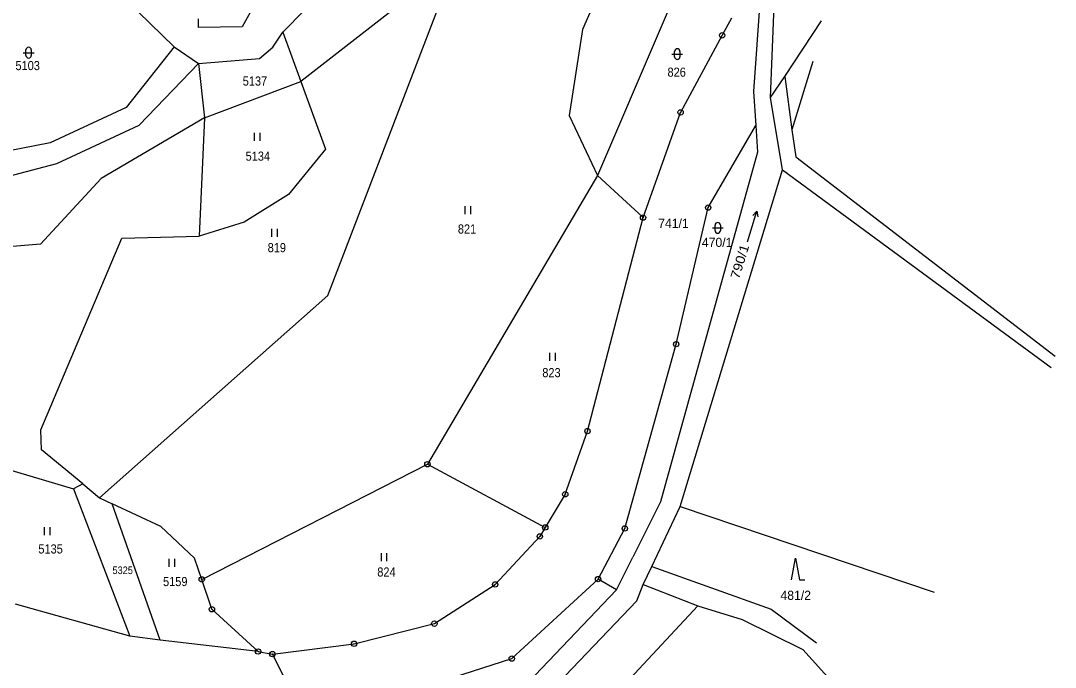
# Model space of a CAD drawing. Extents: x -665688 to -664583, y -1006118 to -1004927.
# Drawn here: x -664775.4 to -664582.7, y -1005645.6 to -1005525.2 of the extents above; entities that cross this region are included whole.
import ezdxf
from ezdxf.enums import TextEntityAlignment as Align

# ---------------------------------------------------------------- set-up
doc = ezdxf.new("R2010")
doc.units = 0
doc.header["$LTSCALE"] = 0.68
for name, color, linetype, lineweight in [('1', 7, 'Continuous', 25), ('13', 7, 'Continuous', 25), ('24', 7, 'Continuous', 25), ('25', 7, 'Continuous', 25)]:
    doc.layers.add(name, color=color, linetype=linetype, lineweight=lineweight)
doc.layers.add('18', color=7, linetype='Continuous')

msp = doc.modelspace()

# ---------------------------------------------------------------- linework, layer by layer
at = {"layer": '1'}
for p, q in [((-664637.47, -1005518.22), (-664638.88, -1005538.4)), ((-664635.72, -1005539.55), (-664634.86, -1005516.66)), ((-664753.52, -1005523.57), (-664746.83, -1005530.12)), ((-664633.1, -1005535.6), (-664626.24, -1005525.26)), ((-664746.83, -1005530.12), (-664742.26, -1005533.2)), ((-664742.26, -1005533.2), (-664741.2, -1005543.33)), ((-664627.87, -1005532.84), (-664631.74, -1005545.57)), ((-664635.72, -1005539.55), (-664633.1, -1005535.6)), ((-664633.1, -1005535.6), (-664631.74, -1005545.57)), ((-664741.2, -1005543.33), (-664723.24, -1005536.54)), ((-664741.2, -1005543.33), (-664742.16, -1005565.36)), ((-664647.35, -1005560.03), (-664638.47, -1005544.74)), ((-664631.74, -1005545.57), (-664631.05, -1005550.6)), ((-664638.14, -1005549.72), (-664656.22, -1005614.79)), ((-664631.05, -1005550.6), (-664582.69, -1005587.66)), ((-664633.51, -1005553.01), (-664583.48, -1005589.82)), ((-664659.48, -1005561.89), (-664667.97, -1005554.06)), ((-664741.69, -1005629.24), (-664699.64, -1005607.8)), ((-664763.84, -1005611.47), (-664765.6, -1005612.38)), ((-664673.97, -1005613.4), (-664677.71, -1005619.57)), ((-664656.22, -1005614.79), (-664661.41, -1005625.11)), ((-664652.59, -1005615.68), (-664605.24, -1005631.61)), ((-664667.85, -1005629.18), (-664662.88, -1005619.76)), ((-664664.44, -1005631.16), (-664661.41, -1005625.11)), ((-664657.84, -1005626.82), (-664635.61, -1005634.8)), ((-664664.44, -1005631.16), (-664667.85, -1005629.18)), ((-664660.62, -1005633.25), (-664659.43, -1005630.2)), ((-664659.43, -1005630.2), (-664649.3, -1005634.13)), ((-664664.44, -1005631.16), (-664682.13, -1005649.71)), ((-664678.66, -1005652.03), (-664660.62, -1005633.25)), ((-664649.3, -1005634.13), (-664641.05, -1005636.72)), ((-664635.61, -1005634.8), (-664627.17, -1005641.05)), ((-664641.05, -1005636.72), (-664629.72, -1005642.29)), ((-664749.4, -1005640.58), (-664755.06, -1005639.78)), ((-664629.72, -1005642.29), (-664623.93, -1005648.66))]:
    msp.add_line(p, q, dxfattribs=at)
for points in [[(-664685.29, -1005447.42), (-664678.21, -1005458.37), (-664669.44, -1005467.93), (-664668.54, -1005477.26), (-664674.88, -1005479.83), (-664681.01, -1005483.45), (-664689.57, -1005496.01), (-664699.21, -1005490.29), (-664709.59, -1005492.53), (-664717.15, -1005498.25), (-664721.04, -1005508.79), (-664724.28, -1005514.32), (-664727.9, -1005516.23), (-664729.33, -1005517.63), (-664734.13, -1005526.39), (-664742.32, -1005526.52), (-664742.32, -1005524.88)], [(-664663.52, -1005487.96), (-664655.75, -1005492.6), (-664670.76, -1005526.88), (-664673.24, -1005542.89), (-664667.97, -1005554.06), (-664699.64, -1005607.8)], [(-664643.02, -1005495.8), (-664644.05, -1005498.2), (-664667.97, -1005554.06)], [(-664699.89, -1005512.36), (-664705.92, -1005523.12), (-664723.24, -1005536.54)], [(-664760.73, -1005614.05), (-664718.22, -1005576.38), (-664695.53, -1005517.33)], [(-664746.83, -1005530.12), (-664755.79, -1005541.41), (-664769.9, -1005547.96), (-664777.87, -1005549.55), (-664809.58, -1005552.27), (-664806.9, -1005547.53), (-664795.07, -1005526.57), (-664788.63, -1005523.13)], [(-664643.03, -1005524.78), (-664644.74, -1005527.96), (-664652.48, -1005542.3)], [(-664742.26, -1005533.2), (-664730.95, -1005532.27), (-664728.47, -1005530.19), (-664726.59, -1005527.38)], [(-664857.56, -1005568.28), (-664837.85, -1005564.71), (-664809.01, -1005556.42), (-664777.88, -1005554.25), (-664768.66, -1005551.79), (-664753.33, -1005544.68), (-664742.26, -1005533.2)], [(-664652.59, -1005615.68), (-664633.51, -1005553.01), (-664635.72, -1005539.55)], [(-664638.88, -1005538.4), (-664638.47, -1005544.74), (-664638.14, -1005549.72)], [(-664741.2, -1005543.33), (-664760.39, -1005554.64), (-664771.75, -1005566.81), (-664853.43, -1005573.61), (-664857.56, -1005568.28)], [(-664673.97, -1005613.4), (-664669.83, -1005601.64), (-664659.48, -1005561.89), (-664652.48, -1005542.3)], [(-664662.88, -1005619.76), (-664653.31, -1005585.45), (-664647.35, -1005560.03)], [(-664809.2, -1005599.44), (-664765.6, -1005612.38), (-664755.06, -1005639.78), (-664776.38, -1005633.86)], [(-664699.64, -1005607.8), (-664677.71, -1005619.57), (-664678.71, -1005621.24)], [(-664731.2, -1005642.66), (-664749.4, -1005640.58), (-664758.34, -1005615.17)], [(-664659.43, -1005630.2), (-664657.84, -1005626.82), (-664652.59, -1005615.68)], [(-664728.52, -1005643.15), (-664713.31, -1005641.23), (-664698.36, -1005637.48), (-664687.03, -1005630.18), (-664678.71, -1005621.24)], [(-664723.34, -1005653.6), (-664718.83, -1005655.21), (-664683.93, -1005643.99), (-664667.85, -1005629.18)], [(-664695.53, -1005671.67), (-664673.75, -1005660.42), (-664649.3, -1005634.13)]]:
    msp.add_lwpolyline(points, dxfattribs=at)
at = {"layer": '13'}
for p, q in [((-664726.59, -1005527.38), (-664723.24, -1005536.54)), ((-664771.68, -1005601.4), (-664756.56, -1005565.69)), ((-664756.56, -1005565.69), (-664742.16, -1005565.36))]:
    msp.add_line(p, q, dxfattribs=at)
for points in [[(-664701.58, -1005496.46), (-664713.18, -1005504.69), (-664714.32, -1005514.93), (-664726.59, -1005527.38)], [(-664723.24, -1005536.54), (-664718.63, -1005549.18), (-664725.52, -1005557.62), (-664733.81, -1005562.76), (-664742.16, -1005565.36)], [(-664763.84, -1005611.47), (-664771.53, -1005605.1), (-664771.68, -1005601.4)], [(-664763.84, -1005611.47), (-664760.73, -1005614.05), (-664758.34, -1005615.17)], [(-664741.69, -1005629.24), (-664743.04, -1005625.31), (-664749.31, -1005619.42), (-664758.34, -1005615.17)], [(-664731.2, -1005642.66), (-664739.79, -1005634.8), (-664741.69, -1005629.24)], [(-664731.2, -1005642.66), (-664728.52, -1005643.15), (-664723.34, -1005653.6), (-664724.77, -1005653.7)]]:
    msp.add_lwpolyline(points, dxfattribs=at)
at = {"layer": '24'}
for centre, radius in [((-664644.74, -1005527.96), 0.5), ((-664644.74, -1005527.96), 0.032), ((-664652.48, -1005542.3), 0.5), ((-664652.48, -1005542.3), 0.032), ((-664647.35, -1005560.03), 0.5), ((-664647.35, -1005560.03), 0.032), ((-664659.48, -1005561.89), 0.5), ((-664659.48, -1005561.89), 0.032), ((-664653.31, -1005585.45), 0.5), ((-664653.31, -1005585.45), 0.032), ((-664669.83, -1005601.64), 0.5), ((-664669.83, -1005601.64), 0.032), ((-664699.64, -1005607.8), 0.5), ((-664699.64, -1005607.8), 0.032), ((-664673.97, -1005613.4), 0.5), ((-664673.97, -1005613.4), 0.032), ((-664677.71, -1005619.57), 0.5), ((-664677.71, -1005619.57), 0.032), ((-664662.88, -1005619.76), 0.5), ((-664662.88, -1005619.76), 0.032), ((-664678.71, -1005621.24), 0.5), ((-664678.71, -1005621.24), 0.032), ((-664741.69, -1005629.24), 0.5), ((-664741.69, -1005629.24), 0.032), ((-664687.03, -1005630.18), 0.5), ((-664687.03, -1005630.18), 0.032), ((-664667.85, -1005629.18), 0.5), ((-664667.85, -1005629.18), 0.032), ((-664739.79, -1005634.8), 0.5), ((-664739.79, -1005634.8), 0.032), ((-664698.36, -1005637.48), 0.5), ((-664698.36, -1005637.48), 0.032), ((-664713.31, -1005641.23), 0.5), ((-664713.31, -1005641.23), 0.032), ((-664731.2, -1005642.66), 0.5), ((-664731.2, -1005642.66), 0.032), ((-664728.52, -1005643.15), 0.5), ((-664728.52, -1005643.15), 0.032), ((-664683.93, -1005643.99), 0.5), ((-664683.93, -1005643.99), 0.032)]:
    msp.add_circle(centre, radius, dxfattribs=at)
at = {"layer": '25'}
for p, q in [((-664774.93, -1005531.19), (-664772.93, -1005531.19)), ((-664774.43, -1005531.69), (-664774.43, -1005530.69)), ((-664773.43, -1005530.69), (-664773.43, -1005531.69)), ((-664654.11, -1005531.45), (-664652.11, -1005531.45)), ((-664653.61, -1005531.95), (-664653.61, -1005530.95)), ((-664652.61, -1005530.95), (-664652.61, -1005531.95)), ((-664731.837, -1005547.585), (-664731.837, -1005546.085)), ((-664730.803, -1005547.585), (-664730.803, -1005546.085)), ((-664692.597, -1005561.275), (-664692.597, -1005559.775)), ((-664691.563, -1005561.275), (-664691.563, -1005559.775)), ((-664640.052, -1005566.394), (-664638.268, -1005560.666)), ((-664728.637, -1005565.485), (-664728.637, -1005563.985)), ((-664727.603, -1005565.485), (-664727.603, -1005563.985)), ((-664646.57, -1005563.8), (-664644.57, -1005563.8)), ((-664646.07, -1005564.3), (-664646.07, -1005563.3)), ((-664645.07, -1005563.3), (-664645.07, -1005564.3)), ((-664676.817, -1005588.545), (-664676.817, -1005587.045)), ((-664675.783, -1005588.545), (-664675.783, -1005587.045)), ((-664770.967, -1005621.005), (-664770.967, -1005619.505)), ((-664769.933, -1005621.005), (-664769.933, -1005619.505)), ((-664708.217, -1005625.875), (-664708.217, -1005624.375)), ((-664707.183, -1005625.875), (-664707.183, -1005624.375)), ((-664747.747, -1005626.885), (-664747.747, -1005625.385)), ((-664746.713, -1005626.885), (-664746.713, -1005625.385))]:
    msp.add_line(p, q, dxfattribs=at)
for points in [[(-664639.043, -1005561.472), (-664638.268, -1005560.666), (-664638.088, -1005561.77)], [(-664631.83, -1005629.3), (-664631.08, -1005625.3), (-664630.33, -1005629.3), (-664629.33, -1005629.3)]]:
    msp.add_lwpolyline(points, dxfattribs=at)
for centre, start, end in [((-664773.93, -1005530.69), 0.101, 180.00143), ((-664773.93, -1005531.69), 180.10243, 0.00286), ((-664653.11, -1005530.95), 0.101, 180.00143), ((-664653.11, -1005531.95), 180.10243, 0.00286), ((-664645.57, -1005563.3), 0.101, 180.00143), ((-664645.57, -1005564.3), 180.10243, 0.00286)]:
    msp.add_arc(centre, 0.5, start, end, dxfattribs=at)

# ---------------------------------------------------------------- texts
at = {"layer": '18', "width": 0.9}
for s, height, p in [('5103', 1.7, (-664774.1095, -1005534.44)), ('826', 1.7, (-664653.2195, -1005535.67)), ('5137', 1.7, (-664731.7795, -1005537.32)), ('5134', 1.7, (-664731.2395, -1005551.3)), ('821', 1.7, (-664692.2695, -1005564.86)), ('819', 1.7, (-664727.6995, -1005568.33)), ('823', 1.7, (-664676.5395, -1005591.6)), ('5135', 1.7, (-664769.8395, -1005624.42)), ('5325', 1.42, (-664756.41, -1005628.25)), ('824', 1.7, (-664707.2795, -1005628.71)), ('5159', 1.7, (-664746.6195, -1005630.49))]:
    msp.add_text(s, height=height, dxfattribs=at).set_placement(p, align=Align.CENTER)
at = {"layer": '18'}
for s, p in [('741/1', (-664653.82, -1005563.8)), ('470/1', (-664645.68, -1005567.35)), ('481/2', (-664631.04, -1005633.05))]:
    msp.add_text(s, height=1.7, dxfattribs=at).set_placement(p, align=Align.CENTER)
at = {"layer": '18', "width": 1.15}
msp.add_text('790/1', height=1.7, rotation=72.801, dxfattribs=at).set_placement((-664640.6518, -1005570.3203), align=Align.CENTER)

doc.saveas('drawing.dxf')
